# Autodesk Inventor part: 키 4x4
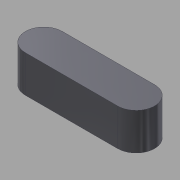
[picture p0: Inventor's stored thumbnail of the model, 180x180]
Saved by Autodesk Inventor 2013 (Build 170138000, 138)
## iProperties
Created: 2014-10
Part Number: 키 4x4
Document SubType Name: Modeling
Designer: KYOUNG IL JANG
Density: 7.86 g/cm^3
Mass: 1.65269 g
Surface Area: 2.35398 cm^2
Volume: 0.210265 cm^3
Material: 강철, 연강
Author: SeoGD™ [www.esajin.kr]
Revision Number: 1
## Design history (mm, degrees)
sketch "스케치1"
  geometry: L1 (-5, -2)-(5, -2); L2 (5, 2)-(-5, 2); A1 r 2 centre (5, 0) between (5, -2) and (5, 2); A2 r 2 centre (-5, 0) between (-5, 2) and (-5, -2); 2 further points
  constraints: 4 end point, 4 point on circle, 4 tangent, 2 centre point, 1 horizontal, 1 horizontal alignment, 1 midpoint, 1 parallel, 1 vertical alignment
  dimensions: "d0" = 4 distance between parallel lines of L1 L2; "d1" = 14 dimension on A1 A2
extrude "돌출1" new body sketch "스케치1" stored distance "d2" = 4; taper "d3" = 0 deg
node "솔리드1"
